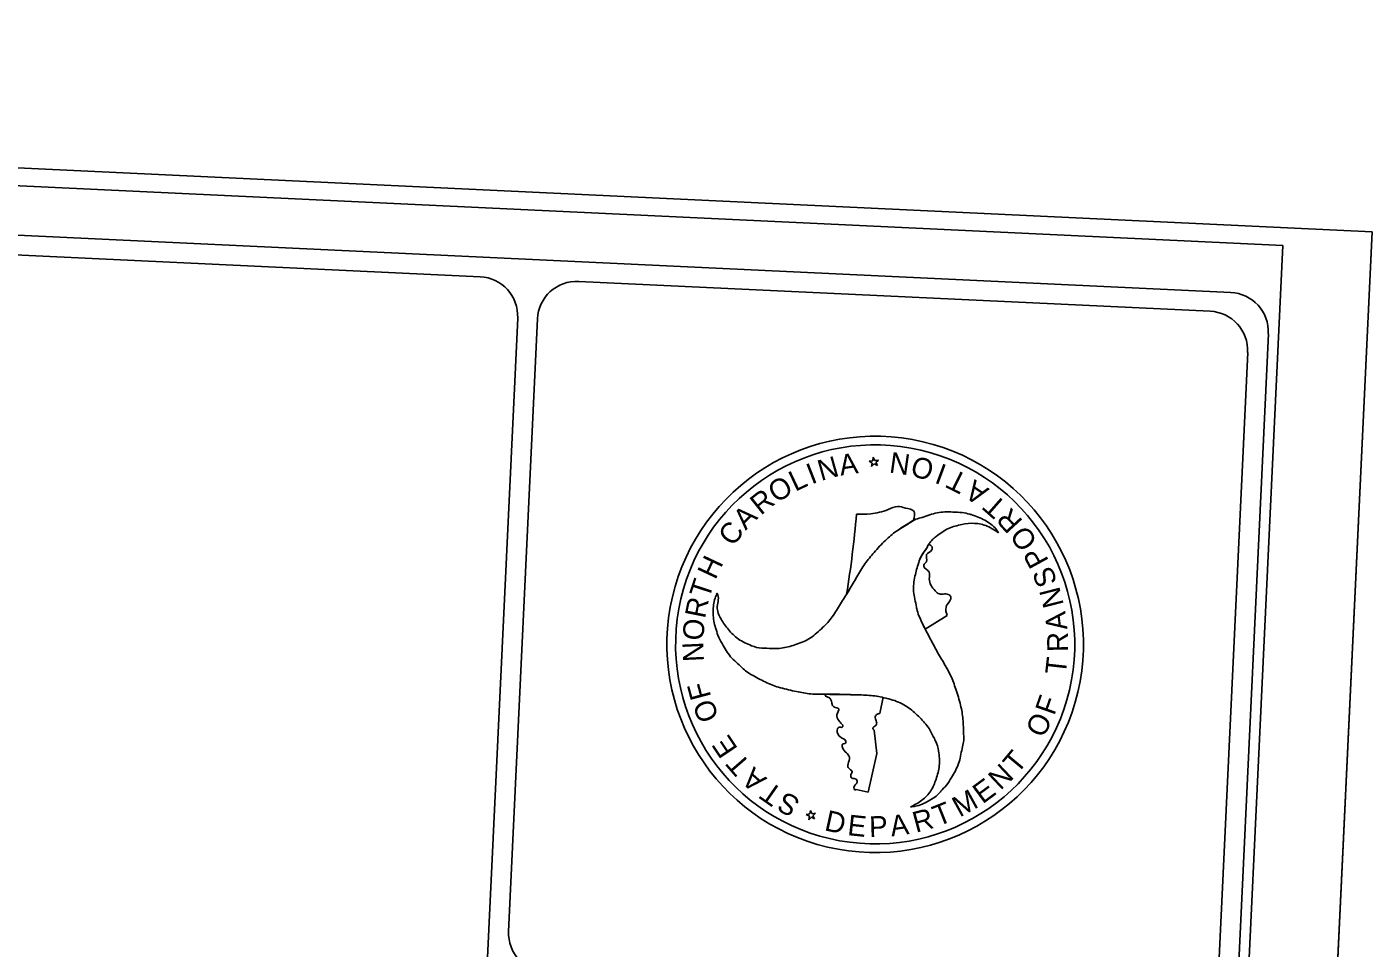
# Model space of a CAD drawing. Extents: x 2166609 to 2169084, y 841593 to 845234.
# Drawn here: x 2168368 to 2169084, y 844744 to 845234 of the extents above; entities that cross this region are included whole.
import ezdxf

# ---------------------------------------------------------------- set-up
doc = ezdxf.new("R2010")
doc.units = 0
for name, color, linetype in [('Sheet Cutting Line CELL', 7, 'Continuous'), ('Sheet Plot Border Inside CELL', 7, 'Continuous'), ('Sheet Plot Border Outside CELL', 7, 'Continuous'), ('Sheet Title CELL', 7, 'Continuous')]:
    doc.layers.add(name, color=color, linetype=linetype)

msp = doc.modelspace()

# ---------------------------------------------------------------- linework, layer by layer
at = {"layer": 'Sheet Cutting Line CELL'}
msp.add_line((2168916.79, 841592.77), (2169083.63, 845125.23), dxfattribs=at)
at = {"layer": 'Sheet Plot Border Inside CELL'}
msp.add_lwpolyline([(2168871.01, 841622.26), (2169036.11, 845118.01), (2166822.87, 845222.54), (2166657.77, 841726.79)], close=True, dxfattribs=at)
at = {"layer": 'Sheet Plot Border Outside CELL'}
msp.add_lwpolyline([(2166776.22, 845234.21), (2166609.39, 841701.75), (2168916.79, 841592.77), (2169083.63, 845125.23)], close=True, dxfattribs=at)
at = {"layer": 'Sheet Title CELL'}
for p, q in [((2168488.78, 842100.73), (2168629.46, 845079.4)), ((2168624.57, 844753.29), (2168639.95, 845078.91)), ((2168839.18, 845014.8), (2168839.18, 845014.8)), ((2168818.39, 845005.4), (2168818.13, 845003.55)), ((2168819.28, 845003.67), (2168818.39, 845005.4)), ((2168818.13, 845003.55), (2168816.26, 845003.22)), ((2168816.26, 845003.22), (2168817.9, 845002.32)), ((2168817.9, 845002.32), (2168817.56, 845000.45)), ((2168817.56, 845000.45), (2168818.94, 845001.8)), ((2168818.94, 845001.8), (2168820.65, 845000.92)), ((2168821.19, 845003.89), (2168819.28, 845003.67)), ((2168819.82, 845002.58), (2168821.19, 845003.89)), ((2168820.65, 845000.92), (2168819.82, 845002.58)), ((2168735.24, 844933.08), (2168735.43, 844932.85)), ((2168735.24, 844933.08), (2168735.43, 844932.85)), ((2168804.25, 844932.6), (2168804.25, 844932.6)), ((2168857.63, 844921.32), (2168846.06, 844913.98)), ((2168846.06, 844913.98), (2168846.06, 844913.98)), ((2168823.61, 844877.73), (2168821.95, 844869.13)), ((2168818.94, 844860.27), (2168820.28, 844847.79)), ((2168820.28, 844847.79), (2168815.76, 844827.27)), ((2168815.76, 844827.27), (2168809.24, 844828.68)), ((2168782.82, 844815.4), (2168784.68, 844815.73)), ((2168784.47, 844814.57), (2168782.82, 844815.4)), ((2168784.13, 844812.66), (2168784.47, 844814.57)), ((2168785.53, 844813.98), (2168784.13, 844812.66)), ((2168784.68, 844815.73), (2168785.02, 844817.6)), ((2168785.02, 844817.6), (2168785.87, 844815.85)), ((2168787.24, 844813.1), (2168785.53, 844813.98)), ((2168785.87, 844815.85), (2168787.79, 844816.1)), ((2168787.79, 844816.1), (2168786.37, 844814.76)), ((2168786.37, 844814.76), (2168787.24, 844813.1))]:
    msp.add_line(p, q, dxfattribs=at)
for points in [[(2169008.52, 845093.04), (2166847.96, 845195.08)], [(2168609.5, 845101.37), (2166857.92, 845184.1)], [(2168997.54, 845083.04), (2168661.91, 845098.9)], [(2168881.91, 841966.53), (2169028.54, 845071.07)], [(2169002.15, 844735.47), (2169017.53, 845061.08)]]:
    msp.add_lwpolyline(points, dxfattribs=at)
for centre, radius, start, end in [((2168608.39, 845080.41), 21, 357.29593, 87.29593), ((2168660.83, 845077.93), 21, 87.29593, 177.29593), ((2169007.44, 845072.07), 21, 357.29593, 87.29593), ((2168996.46, 845062.08), 21, 357.29593, 87.29593), ((2168819.44, 844905.88), 110.71, 79.71706, 259.71706), ((2168819.44, 844905.88), 110.7, 259.71706, 79.71706), ((2168819.44, 844905.88), 106.09, 79.71706, 259.71706), ((2168819.44, 844905.88), 106.09, 259.71706, 79.71706), ((2168228.02, 845025.57), 583.68, 350.8346, 355.04062), ((2168228.02, 845025.57), 583.68, 345.39555, 345.49515), ((2168645.54, 844752.3), 21, 177.29593, 267.29593)]:
    msp.add_arc(centre, radius, start, end, dxfattribs=at)
for points in [[(2168885.01, 844965.27), (2168883.57, 844967.26), (2168877.77, 844971.85), (2168870.51, 844974.87), (2168869.79, 844975.1), (2168865.64, 844975.92), (2168860.66, 844976.26), (2168852.42, 844975.88), (2168844.44, 844973.43), (2168841.09, 844972.41), (2168837.63, 844970.43), (2168830.74, 844966.08), (2168824.88, 844961.17), (2168818.84, 844954.73), (2168813.98, 844948.71), (2168809.73, 844941.84), (2168805.67, 844934.91), (2168801.57, 844928.32), (2168797.19, 844921.41), (2168792.13, 844915.42), (2168791.61, 844914.95), (2168785.06, 844909.34), (2168777.67, 844905.94), (2168770.35, 844904), (2168766.58, 844903.62), (2168761.85, 844903.81), (2168759.11, 844903.81), (2168753.69, 844905.19), (2168746.7, 844908.73), (2168741.38, 844913.79), (2168737.48, 844919.34), (2168735.48, 844925.94), (2168735.43, 844932.85), (2168735.24, 844933.08)], [(2168809.53, 844975.1), (2168817.07, 844975.33), (2168826.32, 844977.59), (2168831.45, 844979.19), (2168835.47, 844978.39), (2168840.11, 844976.58), (2168839.75, 844971.85)], [(2168839.78, 844971.81), (2168837.63, 844970.43), (2168830.74, 844966.08), (2168824.88, 844961.17), (2168818.84, 844954.73), (2168813.98, 844948.71), (2168809.73, 844941.84), (2168805.67, 844934.91), (2168804.25, 844932.6)], [(2168838.25, 844819.45), (2168840.84, 844819.78), (2168847.67, 844822.51), (2168853.94, 844827.24), (2168854.37, 844827.8), (2168857.31, 844830.97), (2168859.99, 844835.08), (2168863.8, 844842.46), (2168865.66, 844850.53), (2168866.45, 844853.95), (2168866.46, 844858.05), (2168866.11, 844866.05), (2168864.84, 844873.55), (2168862.29, 844882.09), (2168859.55, 844889.25), (2168855.67, 844896.36), (2168851.64, 844903.36), (2168847.99, 844910.29), (2168844.32, 844917.46), (2168841.57, 844924.86), (2168841.41, 844925.66), (2168839.87, 844934.08), (2168840.59, 844942.08), (2168842.57, 844949.33), (2168844.07, 844953.02), (2168846.67, 844956.85), (2168848.02, 844959.31), (2168851.91, 844963.31), (2168858.44, 844967.49), (2168865.49, 844969.61), (2168872.31, 844970.24), (2168879, 844968.7), (2168885.01, 844965.27)], [(2168846.06, 844913.98), (2168844.32, 844917.46), (2168841.57, 844924.86), (2168841.41, 844925.66), (2168839.87, 844934.08), (2168840.59, 844942.08), (2168842.57, 844949.33), (2168844.07, 844953.02), (2168846.67, 844956.85), (2168847.95, 844959.12)], [(2168847.97, 844959.08), (2168849.7, 844957.74), (2168849.53, 844956.07), (2168846.71, 844953.61), (2168846.79, 844949.96), (2168845.56, 844948.52), (2168845.33, 844947.46), (2168848.07, 844944.33), (2168848.21, 844940.7), (2168851.35, 844934.29), (2168853.56, 844932.69), (2168858.86, 844932.16), (2168859.65, 844930.59), (2168859.08, 844928.96), (2168857.09, 844925.71), (2168857.63, 844921.32)], [(2168735.43, 844932.85), (2168734.34, 844930.51), (2168733.32, 844923.23), (2168734.34, 844915.44), (2168734.58, 844914.73), (2168735.85, 844910.7), (2168738.05, 844906.26), (2168742.56, 844899.34), (2168748.62, 844893.57), (2168751.23, 844891.23), (2168754.6, 844889.25), (2168761.85, 844885.44), (2168769.04, 844882.83), (2168777.64, 844880.77), (2168785.28, 844879.52), (2168793.29, 844879.36), (2168801.39, 844879.3), (2168809.21, 844879.04), (2168817.25, 844878.69), (2168825.03, 844877.31), (2168825.71, 844877.15), (2168833.75, 844874.26), (2168840.41, 844869.58), (2168845.72, 844864.15), (2168848.07, 844861.09), (2168850.25, 844856.93), (2168851.52, 844854.56), (2168853.14, 844849.16), (2168853.53, 844841.39), (2168851.79, 844834.17), (2168848.97, 844828.01), (2168844.29, 844822.99), (2168838.25, 844819.45)], [(2168809.24, 844828.68), (2168808.59, 844828.57), (2168808.08, 844829.79), (2168809.89, 844832.63), (2168808.85, 844834.42), (2168807.52, 844834.6), (2168806.41, 844836.07), (2168807.21, 844838.09), (2168805.14, 844840.43), (2168805.04, 844842.25), (2168805.7, 844845.93), (2168802.1, 844851.09), (2168802.18, 844852.97), (2168803.42, 844853.22), (2168803.85, 844854.3), (2168800.58, 844856.83), (2168800.15, 844857.41), (2168799.41, 844861.08), (2168800.22, 844861.87), (2168801.89, 844861.83), (2168802.3, 844862.26), (2168801.69, 844863.53), (2168800.03, 844865.4), (2168799.09, 844868.48), (2168800.06, 844871.6), (2168797.54, 844872.62), (2168795.7, 844876.83), (2168794.32, 844877.88), (2168792.81, 844878.35)], [(2168793.09, 844879.37), (2168793.29, 844879.36), (2168801.39, 844879.3), (2168809.21, 844879.04), (2168817.25, 844878.69), (2168823.61, 844877.7)], [(2168821.95, 844869.13), (2168820.22, 844868.58), (2168819.43, 844866.99), (2168820.21, 844864.51), (2168819.8, 844862.82), (2168818.11, 844861.19), (2168818.94, 844860.27)]]:
    msp.add_spline(points, degree=3, dxfattribs=at)

# ---------------------------------------------------------------- texts
for s, height, rotation, p in [('N', 11.03, 15.61239, (2168790.65, 844992.73)), ('A', 11.04, 8.18042, (2168801.1, 844995.57)), ('N', 11.04, 171.92519, (2168838.64, 845006.73)), ('O', 11, 164.67717, (2168851.53, 845003.32)), ('L', 11.01, 25.30184, (2168776.9, 844986.95)), ('I', 11.05, 21.3125, (2168785.61, 844990.84)), ('I', 11.07, 159.54155, (2168858.2, 845000.91)), ('T', 11.02, 153.89164, (2168869.42, 844995.48)), ('O', 11.06, 31.53552, (2168766.88, 844980.8)), ('A', 11.06, 146.80722, (2168880.45, 844988.44)), ('R', 11.03, 38.65512, (2168758.61, 844974.23)), ('T', 11, 138.72017, (2168889.98, 844980.34)), ('A', 11.03, 45.01907, (2168750.62, 844966.21)), ('R', 11.06, 132.62039, (2168898.37, 844971.45)), ('C', 11.01, 52.5161, (2168743.87, 844957.49)), ('O', 11.06, 125.43128, (2168906.18, 844960.63)), ('P', 11.03, 118.73929, (2168911.95, 844950.31)), ('H', 11.02, 64.85845, (2168734.47, 844939.86)), ('T', 11.07, 71.94317, (2168731.04, 844929.61)), ('S', 10.99, 111.54744, (2168916.49, 844938.98)), ('N', 11, 104.33697, (2168919.81, 844926.94)), ('R', 11.04, 78.5928, (2168728.96, 844919.25)), ('A', 11, 97.30534, (2168921.67, 844914.03)), ('O', 11.07, 85.20273, (2168727.99, 844907.62)), ('N', 11.04, 92.70084, (2168728.43, 844896.83)), ('R', 11.05, 90.5522, (2168921.96, 844901.84)), ('T', 11, 83.59559, (2168920.7, 844889.4)), ('F', 11.06, 104.78778, (2168732.32, 844878.02)), ('F', 11.03, 70.68635, (2168914.62, 844867.66)), ('O', 11.05, 111.93462, (2168736.62, 844867.17)), ('O', 11.03, 63.52113, (2168908.84, 844855.63)), ('E', 11, 123.874, (2168746.72, 844850.4)), ('T', 11.02, 50.21744, (2168895.01, 844836.57)), ('T', 11.01, 130.98962, (2168753.77, 844842.21)), ('A', 11.08, 138.04484, (2168762.26, 844834.57)), ('N', 11.06, 43.37544, (2168886.04, 844827.92)), ('E', 11.01, 36.4039, (2168876.53, 844820.74)), ('T', 11.06, 145.09715, (2168771.02, 844828.28)), ('S', 11.03, 151.47331, (2168780.24, 844823.24)), ('M', 11.01, 28.93712, (2168864.36, 844813.75)), ('T', 11.03, 21.70208, (2168852.78, 844808.94)), ('D', 11.04, 347.57006, (2168791.99, 844807.1)), ('E', 10.99, 353.85795, (2168804.39, 844804.49)), ('P', 11.04, 1.39034, (2168816.33, 844803.42)), ('A', 11.02, 7.98291, (2168828.12, 844803.71)), ('R', 11.04, 15.05155, (2168841.05, 844805.67))]:
    msp.add_text(s, height=height, rotation=rotation, dxfattribs=at).set_placement(p)

doc.saveas('drawing.dxf')
